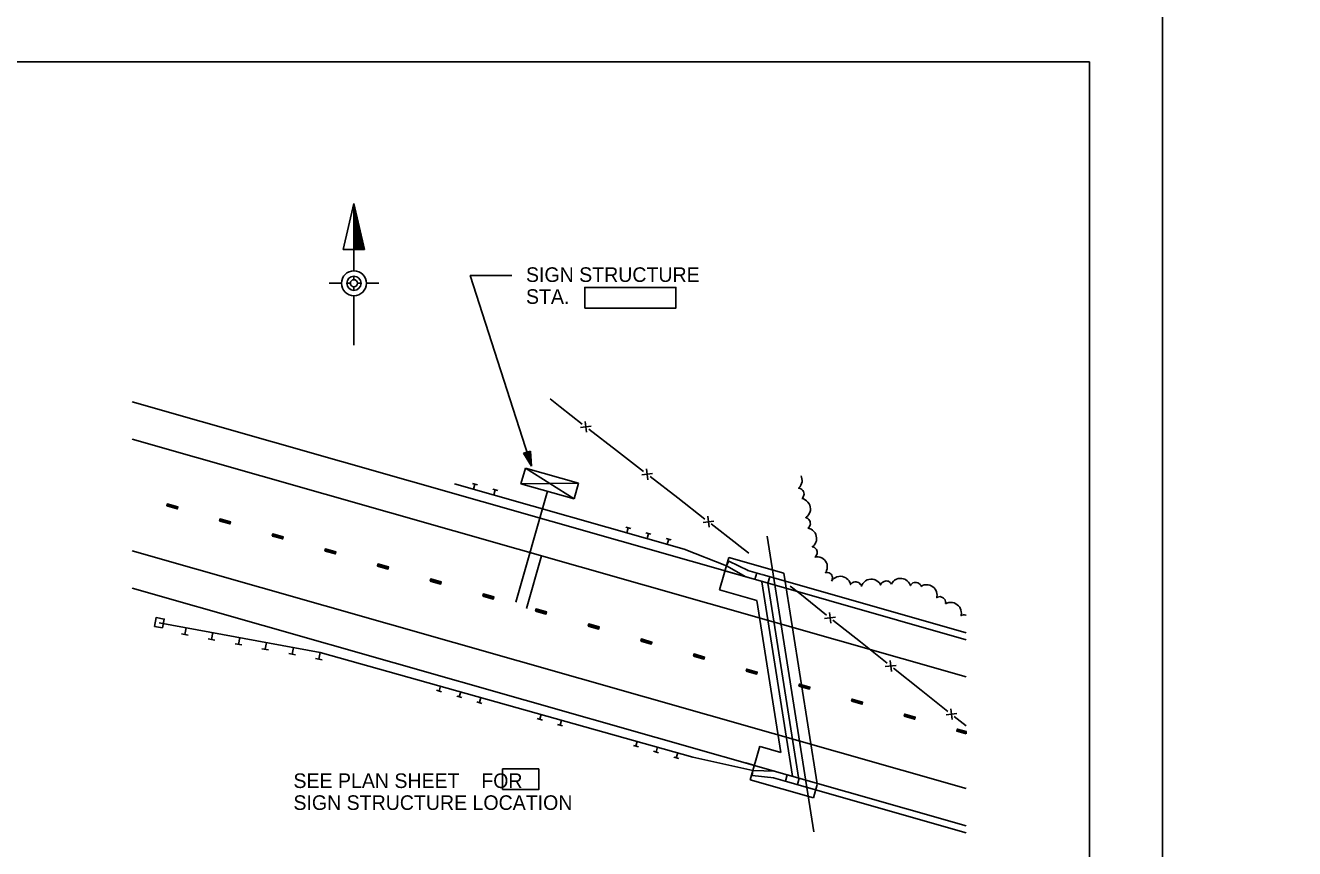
# Model space of a CAD drawing. Extents: x 640117 to 642655, y 297247 to 298435.
# Drawn here: x 640724.9 to 640985.6, y 297665 to 297834 of the extents above; entities that cross this region are included whole.
import ezdxf

# ---------------------------------------------------------------- set-up
doc = ezdxf.new("R2010")
doc.units = 0
for name, color, linetype in [('10', 7, 'Continuous'), ('2', 7, 'Continuous'), ('20', 7, 'Continuous'), ('21', 7, 'Continuous'), ('26', 7, 'Continuous'), ('27', 7, 'Continuous'), ('43', 7, 'Continuous'), ('48', 7, 'Continuous'), ('50', 7, 'Continuous'), ('51', 7, 'Continuous'), ('52', 7, 'Continuous'), ('53', 7, 'Continuous'), ('PLT-BNDY', 7, 'Continuous')]:
    doc.layers.add(name, color=color, linetype=linetype)

msp = doc.modelspace()

# ---------------------------------------------------------------- linework, layer by layer
at = {"layer": '10'}
msp.add_lwpolyline([(640828.84, 297743.48), (640816.31, 297782.59), (640824.86, 297782.59)], dxfattribs=at)
at = {"layer": '2'}
for p, q in [((640157.46, 297826.46), (640943.46, 297826.46)), ((640943.46, 297826.46), (640943.46, 297262.46))]:
    msp.add_line(p, q, dxfattribs=at)
for points in [[(640839.82, 297775.92), (640858.53, 297775.92), (640858.53, 297780.17), (640839.82, 297780.17)], [(640822.93, 297677.07), (640830.35, 297677.07), (640830.35, 297681.32), (640822.93, 297681.32)]]:
    msp.add_lwpolyline(points, close=True, dxfattribs=at)
at = {"layer": '20'}
for points in [[(640884.22, 297741.47), (640884.32, 297741.23), (640884.4, 297740.87), (640884.44, 297740.52), (640884.42, 297740.27), (640884.34, 297739.93), (640884.2, 297739.58), (640884.02, 297739.3), (640883.84, 297739.08), (640883.7, 297738.94), (640883.89, 297738.93), (640884.15, 297738.82), (640884.4, 297738.66), (640884.58, 297738.45), (640884.7, 297738.24), (640884.78, 297738.01), (640884.84, 297737.75), (640884.82, 297737.55), (640884.69, 297737.18), (640884.6, 297736.99), (640884.42, 297736.82)], [(640884.41, 297736.82), (640884.72, 297736.74), (640885.08, 297736.58), (640885.35, 297736.38), (640885.65, 297736.09), (640885.87, 297735.77), (640886.02, 297735.46), (640886.1, 297735.09), (640886.14, 297734.73), (640886.13, 297734.38), (640886.07, 297734.14), (640885.95, 297733.81), (640885.76, 297733.49), (640885.55, 297733.23), (640885.34, 297733.04), (640885.18, 297732.93), (640885.37, 297732.88), (640885.62, 297732.74), (640885.83, 297732.55), (640885.99, 297732.32), (640886.08, 297732.1), (640886.12, 297731.85), (640886.14, 297731.59), (640886.11, 297731.4), (640885.93, 297731.05), (640885.8, 297730.87), (640885.61, 297730.73)], [(640885.61, 297730.73), (640885.92, 297730.67), (640886.28, 297730.53), (640886.56, 297730.35), (640886.86, 297730.07), (640887.11, 297729.77), (640887.26, 297729.47), (640887.36, 297729.11), (640887.41, 297728.76), (640887.42, 297728.41), (640887.37, 297728.17), (640887.26, 297727.84), (640887.09, 297727.52), (640886.89, 297727.25), (640886.68, 297727.05), (640886.53, 297726.93), (640886.72, 297726.89), (640886.97, 297726.77), (640887.2, 297726.59), (640887.37, 297726.37), (640887.47, 297726.16), (640887.52, 297725.93), (640887.56, 297725.66), (640887.52, 297725.47), (640887.36, 297725.12), (640887.24, 297724.94), (640887.06, 297724.79)], [(640887.06, 297724.79), (640887.36, 297724.85), (640887.75, 297724.85), (640888.08, 297724.78), (640888.46, 297724.64), (640888.79, 297724.45), (640889.04, 297724.23), (640889.26, 297723.94), (640889.43, 297723.64), (640889.56, 297723.32), (640889.6, 297723.07), (640889.61, 297722.74), (640889.56, 297722.37), (640889.46, 297722.06), (640889.35, 297721.8), (640889.24, 297721.64), (640889.43, 297721.67), (640889.71, 297721.65), (640889.99, 297721.57), (640890.22, 297721.42), (640890.38, 297721.27), (640890.52, 297721.08), (640890.63, 297720.84), (640890.68, 297720.66), (640890.64, 297720.27), (640890.6, 297720.07), (640890.47, 297719.86)], [(640890.47, 297719.86), (640890.65, 297720.12), (640890.93, 297720.39), (640891.22, 297720.58), (640891.6, 297720.74), (640891.99, 297720.84), (640892.33, 297720.86), (640892.71, 297720.81), (640893.06, 297720.71), (640893.39, 297720.58), (640893.59, 297720.43), (640893.85, 297720.21), (640894.09, 297719.91), (640894.25, 297719.62), (640894.36, 297719.36), (640894.4, 297719.16), (640894.52, 297719.32), (640894.73, 297719.5), (640894.99, 297719.65), (640895.27, 297719.71), (640895.51, 297719.71), (640895.75, 297719.66), (640896, 297719.59), (640896.16, 297719.49), (640896.43, 297719.19), (640896.55, 297719.01), (640896.62, 297718.78)], [(640896.62, 297718.78), (640896.73, 297719.07), (640896.93, 297719.4), (640897.16, 297719.65), (640897.48, 297719.91), (640897.82, 297720.11), (640898.15, 297720.21), (640898.52, 297720.25), (640898.88, 297720.25), (640899.23, 297720.2), (640899.47, 297720.11), (640899.77, 297719.95), (640900.07, 297719.72), (640900.3, 297719.49), (640900.46, 297719.25), (640900.56, 297719.08), (640900.63, 297719.26), (640900.79, 297719.49), (640901.01, 297719.69), (640901.26, 297719.82), (640901.49, 297719.88), (640901.73, 297719.9), (640901.99, 297719.89), (640902.17, 297719.83), (640902.51, 297719.61), (640902.67, 297719.47), (640902.78, 297719.25)], [(640902.78, 297719.25), (640902.94, 297719.53), (640903.18, 297719.83), (640903.44, 297720.04), (640903.8, 297720.24), (640904.16, 297720.38), (640904.49, 297720.43), (640904.86, 297720.42), (640905.21, 297720.36), (640905.55, 297720.27), (640905.77, 297720.14), (640906.04, 297719.94), (640906.3, 297719.67), (640906.49, 297719.4), (640906.61, 297719.14), (640906.68, 297718.96), (640906.78, 297719.13), (640906.96, 297719.34), (640907.21, 297719.5), (640907.47, 297719.59), (640907.7, 297719.62), (640907.94, 297719.59), (640908.2, 297719.55), (640908.37, 297719.46), (640908.66, 297719.19), (640908.79, 297719.03), (640908.87, 297718.8)], [(640908.87, 297718.8), (640909.15, 297718.95), (640909.52, 297719.08), (640909.85, 297719.12), (640910.26, 297719.11), (640910.65, 297719.03), (640910.97, 297718.91), (640911.28, 297718.7), (640911.55, 297718.46), (640911.78, 297718.2), (640911.91, 297717.98), (640912.03, 297717.67), (640912.12, 297717.3), (640912.14, 297716.97), (640912.12, 297716.69), (640912.08, 297716.49), (640912.25, 297716.59), (640912.52, 297716.66), (640912.81, 297716.68), (640913.09, 297716.61), (640913.3, 297716.52), (640913.5, 297716.38), (640913.69, 297716.19), (640913.8, 297716.02), (640913.9, 297715.64), (640913.93, 297715.44), (640913.89, 297715.2)], [(640913.89, 297715.2), (640914.16, 297715.34), (640914.54, 297715.46), (640914.88, 297715.49), (640915.29, 297715.47), (640915.68, 297715.38), (640915.99, 297715.24), (640916.3, 297715.03), (640916.57, 297714.78), (640916.81, 297714.52), (640916.92, 297714.29), (640917.05, 297713.96), (640917.12, 297713.6), (640917.14, 297713.27), (640917.11, 297712.98), (640917.07, 297712.79), (640917.24, 297712.88), (640917.52, 297712.94), (640917.81, 297712.95), (640918.09, 297712.88), (640918.14, 297712.85)]]:
    msp.add_lwpolyline(points, dxfattribs=at)
at = {"layer": '21'}
for p, q in [((640839.89, 297752.66), (640840.18, 297750.42)), ((640838.92, 297751.4), (640841.15, 297751.68)), ((640852.47, 297742.92), (640852.76, 297740.68)), ((640851.51, 297741.66), (640853.73, 297741.95)), ((640864.09, 297731.91), (640866.32, 297732.2)), ((640865.06, 297733.18), (640865.34, 297730.94)), ((640890.06, 297713.46), (640890.31, 297711.22)), ((640889.07, 297712.21), (640891.3, 297712.47)), ((640902.52, 297703.57), (640902.77, 297701.33)), ((640901.53, 297702.32), (640903.76, 297702.58)), ((640913.99, 297692.42), (640916.23, 297692.68)), ((640914.98, 297693.67), (640915.24, 297691.43))]:
    msp.add_line(p, q, dxfattribs=at)
for points in [[(640832.69, 297757.26), (640833.74, 297756.44)], [(640833.73, 297756.44), (640834.73, 297755.64), (640839.31, 297752.1)], [(640840.62, 297751.09), (640846.31, 297746.68)], [(640846.31, 297746.68), (640851.89, 297742.36)], [(640853.21, 297741.35), (640858.9, 297736.94)], [(640858.9, 297736.94), (640864.48, 297732.62)], [(640865.78, 297731.61), (640871.06, 297727.53), (640871.47, 297727.19)], [(640871.47, 297727.19), (640873.47, 297725.61)], [(640882, 297718.84), (640883.94, 297717.3)], [(640883.94, 297717.3), (640889.46, 297712.91)], [(640890.76, 297711.88), (640896.4, 297707.4)], [(640896.4, 297707.4), (640901.92, 297703.02)], [(640903.22, 297701.99), (640908.86, 297697.51)], [(640908.86, 297697.51), (640914.39, 297693.12)], [(640915.68, 297692.09), (640918.14, 297690.14)]]:
    msp.add_lwpolyline(points, dxfattribs=at)
at = {"layer": '26'}
for p, q in [((640746.87, 297756.65), (640875.82, 297719.91)), ((640746.87, 297749.01), (640918.14, 297700.21)), ((640746.87, 297726.09), (640918.14, 297677.29)), ((640746.87, 297718.45), (640881.39, 297680.12))]:
    msp.add_line(p, q, dxfattribs=at)
at = {"layer": '27'}
for p, q in [((640860.2, 297726.45), (640813.07, 297739.87)), ((640817.79, 297739.64), (640816.75, 297739.93)), ((640817.27, 297739.79), (640816.98, 297738.75)), ((640821.94, 297738.47), (640820.9, 297738.76)), ((640821.42, 297738.61), (640821.13, 297737.58)), ((640849.26, 297730.67), (640848.22, 297730.97)), ((640848.74, 297730.82), (640848.45, 297729.78)), ((640853.41, 297729.5), (640852.37, 297729.8)), ((640852.89, 297729.65), (640852.6, 297728.61)), ((640857.56, 297728.33), (640856.52, 297728.62)), ((640857.04, 297728.48), (640856.75, 297727.44)), ((640868.92, 297723.01), (640860.2, 297726.45)), ((640785.47, 297705.21), (640752.44, 297711.33)), ((640758.38, 297708.8), (640757, 297709.06)), ((640757.69, 297708.93), (640757.94, 297710.3)), ((640763.19, 297707.91), (640763.45, 297709.29)), ((640768.7, 297706.89), (640768.95, 297708.27)), ((640763.88, 297707.78), (640762.51, 297708.04)), ((640769.39, 297706.76), (640768.01, 297707.02)), ((640774.89, 297705.74), (640773.52, 297706)), ((640774.2, 297705.87), (640774.46, 297707.25)), ((640779.71, 297704.85), (640779.97, 297706.23)), ((640780.4, 297704.73), (640779.02, 297704.98)), ((640785.89, 297703.71), (640784.52, 297703.96)), ((640785.2, 297703.84), (640785.46, 297705.21)), ((640809.88, 297697.31), (640810.18, 297698.35)), ((640810.4, 297697.17), (640809.36, 297697.46)), ((640814.55, 297695.97), (640813.51, 297696.27)), ((640814.03, 297696.12), (640814.33, 297697.16)), ((640818.17, 297694.93), (640818.47, 297695.97)), ((640818.69, 297694.78), (640817.66, 297695.08)), ((640830.59, 297691.5), (640830.88, 297692.54)), ((640831.1, 297691.36), (640830.07, 297691.65)), ((640835.25, 297690.16), (640834.21, 297690.46)), ((640834.73, 297690.31), (640835.03, 297691.35)), ((640850.82, 297685.82), (640849.79, 297686.12)), ((640850.3, 297685.97), (640850.6, 297687.01)), ((640854.97, 297684.63), (640853.93, 297684.93)), ((640854.45, 297684.78), (640854.75, 297685.82)), ((640859.11, 297683.44), (640858.08, 297683.74)), ((640858.6, 297683.59), (640858.89, 297684.63))]:
    msp.add_line(p, q, dxfattribs=at)
msp.add_lwpolyline([(640753.13, 297710.26), (640753.47, 297712.07), (640751.8, 297712.37), (640751.46, 297710.57)], close=True, dxfattribs=at)
msp.add_lwpolyline([(640785.47, 297705.21), (640862.03, 297683.73), (640874.35, 297681)], dxfattribs=at)
at = {"layer": '43'}
for p, q in [((640826.7, 297739.86), (640827.62, 297743.09)), ((640827.62, 297743.09), (640838.53, 297739.98)), ((640827.62, 297743.09), (640837.61, 297736.76)), ((640838.53, 297739.98), (640826.7, 297739.86)), ((640826.7, 297739.86), (640837.61, 297736.76)), ((640837.61, 297736.75), (640838.52, 297739.98)), ((640825.68, 297715.58), (640832.15, 297738.31)), ((640827.86, 297714.26), (640830.93, 297725.05))]:
    msp.add_line(p, q, dxfattribs=at)
at = {"layer": '48'}
for points in [[(640753.97, 297735.3), (640756.13, 297734.68), (640756.25, 297735.12), (640754.09, 297735.73)], [(640754.03, 297735.33), (640756.1, 297734.74), (640756.19, 297735.08), (640754.12, 297735.66)], [(640754.09, 297735.36), (640756.06, 297734.8), (640756.13, 297735.04), (640754.15, 297735.61)], [(640754.14, 297735.4), (640756.04, 297734.86), (640756.08, 297735.02), (640754.19, 297735.55)], [(640754.18, 297735.42), (640756.01, 297734.9), (640756.04, 297734.99), (640754.21, 297735.51)], [(640754.22, 297735.44), (640755.98, 297734.93), (640756, 297734.97), (640754.23, 297735.47)], [(640764.78, 297732.21), (640766.94, 297731.6), (640767.07, 297732.03), (640764.91, 297732.65)], [(640764.84, 297732.25), (640766.91, 297731.66), (640767.01, 297732), (640764.94, 297732.59)], [(640764.91, 297732.28), (640766.88, 297731.72), (640766.95, 297731.96), (640764.97, 297732.52)], [(640764.95, 297732.31), (640766.85, 297731.78), (640766.89, 297731.93), (640765, 297732.47)], [(640764.99, 297732.34), (640766.83, 297731.81), (640766.86, 297731.91), (640765.03, 297732.43)], [(640765.04, 297732.35), (640766.8, 297731.85), (640766.81, 297731.89), (640765.05, 297732.39)], [(640775.6, 297729.13), (640777.76, 297728.52), (640777.88, 297728.95), (640775.73, 297729.57)], [(640775.66, 297729.16), (640777.73, 297728.57), (640777.82, 297728.92), (640775.76, 297729.51)], [(640775.72, 297729.2), (640777.7, 297728.64), (640777.76, 297728.88), (640775.79, 297729.44)], [(640775.77, 297729.23), (640777.66, 297728.69), (640777.72, 297728.85), (640775.82, 297729.39)], [(640775.82, 297729.25), (640777.64, 297728.73), (640777.67, 297728.83), (640775.84, 297729.35)], [(640775.85, 297729.27), (640777.62, 297728.77), (640777.63, 297728.81), (640775.86, 297729.31)], [(640786.42, 297726.05), (640788.58, 297725.44), (640788.7, 297725.87), (640786.54, 297726.48)], [(640786.47, 297726.08), (640788.54, 297725.49), (640788.64, 297725.84), (640786.57, 297726.43)], [(640786.53, 297726.12), (640788.51, 297725.56), (640788.58, 297725.8), (640786.61, 297726.36)], [(640786.59, 297726.15), (640788.48, 297725.61), (640788.52, 297725.77), (640786.63, 297726.31)], [(640786.63, 297726.17), (640788.46, 297725.65), (640788.49, 297725.74), (640786.65, 297726.27)], [(640786.67, 297726.19), (640788.44, 297725.69), (640788.45, 297725.72), (640786.68, 297726.22)], [(640797.23, 297722.97), (640799.4, 297722.35), (640799.52, 297722.78), (640797.35, 297723.4)], [(640797.29, 297723.01), (640799.36, 297722.41), (640799.46, 297722.75), (640797.38, 297723.34)], [(640797.35, 297723.04), (640799.33, 297722.48), (640799.4, 297722.72), (640797.42, 297723.28)], [(640797.4, 297723.06), (640799.3, 297722.52), (640799.34, 297722.69), (640797.45, 297723.23)], [(640797.45, 297723.09), (640799.27, 297722.56), (640799.3, 297722.66), (640797.48, 297723.19)], [(640797.48, 297723.11), (640799.25, 297722.6), (640799.26, 297722.64), (640797.49, 297723.15)], [(640808.05, 297719.88), (640810.21, 297719.27), (640810.33, 297719.7), (640808.17, 297720.32)], [(640808.1, 297719.92), (640810.17, 297719.33), (640810.27, 297719.67), (640808.2, 297720.26)], [(640808.17, 297719.95), (640810.14, 297719.39), (640810.21, 297719.63), (640808.23, 297720.2)], [(640808.22, 297719.98), (640810.12, 297719.44), (640810.16, 297719.61), (640808.27, 297720.14)], [(640808.26, 297720), (640810.1, 297719.49), (640810.12, 297719.58), (640808.29, 297720.1)], [(640808.3, 297720.03), (640810.07, 297719.52), (640810.08, 297719.56), (640808.31, 297720.07)], [(640818.87, 297716.8), (640821.02, 297716.19), (640821.15, 297716.62), (640818.99, 297717.24)], [(640818.92, 297716.84), (640820.99, 297716.25), (640821.09, 297716.59), (640819.02, 297717.18)], [(640818.99, 297716.87), (640820.96, 297716.31), (640821.03, 297716.55), (640819.05, 297717.12)], [(640819.03, 297716.9), (640820.93, 297716.36), (640820.98, 297716.52), (640819.08, 297717.06)], [(640819.08, 297716.92), (640820.9, 297716.41), (640820.93, 297716.5), (640819.11, 297717.02)], [(640819.12, 297716.95), (640820.88, 297716.44), (640820.89, 297716.48), (640819.13, 297716.98)], [(640829.68, 297713.72), (640831.84, 297713.1), (640831.97, 297713.54), (640829.8, 297714.15)], [(640829.74, 297713.76), (640831.81, 297713.17), (640831.9, 297713.5), (640829.83, 297714.09)], [(640829.8, 297713.79), (640831.77, 297713.23), (640831.84, 297713.47), (640829.87, 297714.03)], [(640829.85, 297713.81), (640831.74, 297713.28), (640831.79, 297713.44), (640829.9, 297713.99)], [(640829.89, 297713.84), (640831.72, 297713.32), (640831.75, 297713.42), (640829.92, 297713.94)], [(640829.93, 297713.86), (640831.7, 297713.36), (640831.71, 297713.39), (640829.94, 297713.9)], [(640840.49, 297710.64), (640842.66, 297710.02), (640842.78, 297710.46), (640840.62, 297711.07)], [(640840.55, 297710.67), (640842.62, 297710.08), (640842.72, 297710.42), (640840.65, 297711.01)], [(640840.61, 297710.7), (640842.59, 297710.14), (640842.66, 297710.39), (640840.69, 297710.95)], [(640840.67, 297710.73), (640842.56, 297710.2), (640842.61, 297710.36), (640840.71, 297710.9)], [(640840.71, 297710.76), (640842.54, 297710.24), (640842.57, 297710.34), (640840.74, 297710.85)], [(640840.75, 297710.78), (640842.52, 297710.28), (640842.53, 297710.32), (640840.76, 297710.82)], [(640851.31, 297707.56), (640853.47, 297706.94), (640853.6, 297707.37), (640851.43, 297707.99)], [(640851.37, 297707.59), (640853.44, 297707), (640853.54, 297707.34), (640851.46, 297707.93)], [(640851.43, 297707.62), (640853.4, 297707.06), (640853.48, 297707.31), (640851.5, 297707.87)], [(640851.48, 297707.66), (640853.38, 297707.11), (640853.42, 297707.28), (640851.53, 297707.82)], [(640851.53, 297707.68), (640853.36, 297707.16), (640853.38, 297707.25), (640851.56, 297707.78)], [(640851.56, 297707.7), (640853.33, 297707.2), (640853.34, 297707.23), (640851.57, 297707.73)], [(640862.13, 297704.48), (640864.29, 297703.86), (640864.41, 297704.29), (640862.25, 297704.91)], [(640862.18, 297704.51), (640864.26, 297703.92), (640864.35, 297704.26), (640862.28, 297704.85)], [(640862.25, 297704.55), (640864.22, 297703.98), (640864.29, 297704.22), (640862.32, 297704.79)], [(640862.3, 297704.57), (640864.2, 297704.03), (640864.24, 297704.2), (640862.35, 297704.74)], [(640862.35, 297704.59), (640864.17, 297704.07), (640864.2, 297704.17), (640862.37, 297704.7)], [(640862.38, 297704.62), (640864.15, 297704.11), (640864.16, 297704.15), (640862.39, 297704.65)], [(640872.94, 297701.39), (640875.1, 297700.78), (640875.23, 297701.21), (640873.07, 297701.83)], [(640873, 297701.42), (640875.07, 297700.84), (640875.17, 297701.18), (640873.1, 297701.77)], [(640873.07, 297701.46), (640875.04, 297700.9), (640875.11, 297701.14), (640873.13, 297701.7)], [(640873.11, 297701.49), (640875.01, 297700.95), (640875.05, 297701.11), (640873.16, 297701.65)], [(640873.15, 297701.51), (640874.99, 297700.99), (640875.01, 297701.09), (640873.18, 297701.61)], [(640873.19, 297701.53), (640874.96, 297701.03), (640874.98, 297701.07), (640873.21, 297701.57)], [(640883.76, 297698.31), (640885.93, 297697.7), (640886.05, 297698.13), (640883.88, 297698.74)], [(640883.82, 297698.35), (640885.89, 297697.75), (640885.98, 297698.1), (640883.92, 297698.69)], [(640883.88, 297698.38), (640885.85, 297697.82), (640885.93, 297698.06), (640883.95, 297698.63)], [(640883.94, 297698.41), (640885.82, 297697.87), (640885.87, 297698.03), (640883.98, 297698.57)], [(640883.98, 297698.43), (640885.8, 297697.91), (640885.83, 297698.01), (640884, 297698.53)], [(640884.01, 297698.45), (640885.78, 297697.95), (640885.79, 297697.99), (640884.02, 297698.49)], [(640894.57, 297695.23), (640896.74, 297694.61), (640896.86, 297695.05), (640894.7, 297695.67)], [(640894.64, 297695.27), (640896.7, 297694.67), (640896.8, 297695.01), (640894.73, 297695.6)], [(640894.7, 297695.3), (640896.67, 297694.73), (640896.74, 297694.98), (640894.77, 297695.54)], [(640894.74, 297695.32), (640896.64, 297694.79), (640896.69, 297694.95), (640894.79, 297695.49)], [(640894.79, 297695.35), (640896.62, 297694.83), (640896.65, 297694.92), (640894.82, 297695.45)], [(640894.83, 297695.37), (640896.6, 297694.87), (640896.61, 297694.9), (640894.84, 297695.41)], [(640905.39, 297692.15), (640907.55, 297691.53), (640907.68, 297691.96), (640905.51, 297692.59)], [(640905.45, 297692.18), (640907.52, 297691.59), (640907.62, 297691.93), (640905.55, 297692.52)], [(640905.51, 297692.21), (640907.49, 297691.65), (640907.55, 297691.9), (640905.58, 297692.46)], [(640905.56, 297692.24), (640907.46, 297691.7), (640907.5, 297691.87), (640905.62, 297692.4)], [(640905.61, 297692.27), (640907.43, 297691.75), (640907.46, 297691.84), (640905.64, 297692.37)], [(640905.65, 297692.28), (640907.41, 297691.79), (640907.42, 297691.82), (640905.65, 297692.33)]]:
    msp.add_lwpolyline(points, close=True, dxfattribs=at)
for points in [[(640918.14, 297688.98), (640916.33, 297689.5), (640916.21, 297689.07), (640918.14, 297688.51)], [(640918.14, 297688.93), (640916.36, 297689.44), (640916.26, 297689.1), (640918.14, 297688.57)], [(640918.14, 297688.88), (640916.39, 297689.38), (640916.33, 297689.13), (640918.14, 297688.62)], [(640918.14, 297688.84), (640916.42, 297689.32), (640916.38, 297689.16), (640918.14, 297688.66)], [(640918.14, 297688.8), (640916.45, 297689.28), (640916.42, 297689.19), (640918.14, 297688.7)], [(640918.14, 297688.77), (640916.47, 297689.24), (640916.46, 297689.21), (640918.14, 297688.73)], [(640918.14, 297688.51), (640918.14, 297688.98)], [(640918.14, 297688.57), (640918.14, 297688.93)], [(640918.14, 297688.62), (640918.14, 297688.88)], [(640918.14, 297688.66), (640918.14, 297688.84)], [(640918.14, 297688.7), (640918.14, 297688.8)], [(640918.14, 297688.73), (640918.14, 297688.77)]]:
    msp.add_lwpolyline(points, dxfattribs=at)
at = {"layer": '50'}
msp.add_line((640877.27, 297729.08), (640886.86, 297668.38), dxfattribs=at)
at = {"layer": '51'}
for p, q in [((640867.51, 297718.05), (640869.4, 297724.7)), ((640868.92, 297723.01), (640869.39, 297723.96)), ((640869.39, 297723.96), (640873.36, 297722.04)), ((640869.4, 297724.7), (640880.72, 297721.47)), ((640868.75, 297721.92), (640875.82, 297719.91)), ((640872.86, 297720.75), (640868.92, 297723.01)), ((640873.31, 297722.05), (640876.2, 297721.23)), ((640875.11, 297721.54), (640874.73, 297720.22)), ((640876.24, 297721.22), (640918.14, 297709.28)), ((640880.72, 297721.47), (640887.55, 297678.25)), ((640875.86, 297719.9), (640918.14, 297707.85)), ((640876.18, 297719.72), (640882.49, 297679.81)), ((640877.79, 297720.78), (640877.42, 297719.46)), ((640877.42, 297719.46), (640883.79, 297679.12)), ((640867.51, 297718.05), (640875.17, 297715.86)), ((640875.17, 297715.86), (640880.09, 297684.72)), ((640875.74, 297685.96), (640873.76, 297679.06)), ((640875.86, 297685.92), (640880.09, 297684.72)), ((640874.75, 297682.01), (640872.89, 297682.54)), ((640874.32, 297681.01), (640874.21, 297679.94)), ((640874.21, 297679.94), (640878.6, 297679.49)), ((640878.83, 297680.85), (640874.35, 297681)), ((640878.55, 297679.5), (640881.44, 297678.67)), ((640881.01, 297678.79), (640881.39, 297680.12)), ((640881.39, 297680.12), (640918.14, 297669.64)), ((640873.76, 297679.06), (640886.76, 297675.36)), ((640881.47, 297678.66), (640918.14, 297668.21)), ((640883.5, 297678.09), (640883.79, 297679.12)), ((640886.76, 297675.36), (640887.54, 297678.12))]:
    msp.add_line(p, q, dxfattribs=at)
at = {"layer": '52'}
for p, q in [((640828.68, 297746.57), (640827.24, 297746.13)), ((640827.24, 297746.13), (640828.84, 297743.48)), ((640828.51, 297746.33), (640827.51, 297746.02)), ((640827.51, 297746.02), (640828.62, 297744.18)), ((640828.35, 297746.09), (640827.78, 297745.92)), ((640827.78, 297745.92), (640828.41, 297744.88)), ((640828, 297745.91), (640828.19, 297745.58)), ((640828.19, 297745.58), (640828.18, 297745.95)), ((640828.41, 297744.88), (640828.35, 297746.09)), ((640828.62, 297744.18), (640828.51, 297746.33)), ((640828.84, 297743.48), (640828.68, 297746.57))]:
    msp.add_line(p, q, dxfattribs=at)
at = {"layer": '53'}
for p, q in [((640790.22, 297787.93), (640792.41, 297797.39)), ((640794.59, 297787.93), (640792.41, 297797.39)), ((640792.41, 297783.57), (640792.41, 297797.39)), ((640794.59, 297787.93), (640790.22, 297787.93)), ((640792.41, 297781.75), (640792.41, 297782.47)), ((640789.86, 297781.02), (640787.31, 297781.02)), ((640791.7, 297781.02), (640790.96, 297781.02)), ((640792.41, 297781.02), (640792.41, 297781.02)), ((640792.41, 297779.58), (640792.41, 297780.29)), ((640793.87, 297781.02), (640793.12, 297781.02)), ((640797.5, 297781.02), (640794.94, 297781.02)), ((640792.41, 297768.28), (640792.41, 297778.46))]:
    msp.add_line(p, q, dxfattribs=at)
msp.add_lwpolyline([(640792.51, 297796.72), (640792.51, 297787.99), (640794.48, 297787.99), (640792.62, 297796.29), (640792.62, 297788.1), (640794.37, 297788.1), (640792.73, 297795.41), (640792.73, 297788.21), (640794.26, 297788.21), (640792.84, 297794.65), (640792.84, 297788.32), (640794.15, 297788.32), (640792.95, 297793.77), (640792.95, 297788.42), (640794.04, 297788.42), (640793.06, 297793.01), (640793.06, 297788.54), (640793.93, 297788.54), (640793.17, 297792.14), (640793.17, 297788.64), (640793.83, 297788.64), (640793.28, 297791.37), (640793.28, 297788.75), (640793.72, 297788.75), (640793.39, 297790.5), (640793.39, 297788.86), (640793.61, 297788.86), (640793.5, 297789.52), (640793.5, 297788.97), (640792.51, 297787.99), (640792.51, 297796.72), (640793.5, 297789.52), (640793.5, 297788.97), (640794.48, 297787.99)], dxfattribs=at)
for radius in [2.55, 1.46, 0.728]:
    msp.add_circle((640792.41, 297781.02), radius, dxfattribs=at)
at = {"layer": 'PLT-BNDY'}
for points in [[(640117.46, 297841.46), (640958.46, 297841.46), (640958.46, 297247.46), (640117.46, 297247.46)], [(640958.46, 297841.46), (641799.46, 297841.46), (641799.46, 297247.46), (640958.46, 297247.46)]]:
    msp.add_lwpolyline(points, close=True, dxfattribs=at)

# ---------------------------------------------------------------- texts
at = {"layer": '2'}
for s, p in [('SIGN STRUCTURE', (640827.74, 297781.29)), ('STA.', (640827.74, 297776.79)), ('SEE PLAN SHEET    FOR', (640779.99, 297677.4)), ('SIGN STRUCTURE LOCATION', (640779.99, 297672.9))]:
    msp.add_text(s, height=3, dxfattribs=at).set_placement(p)

doc.saveas('drawing.dxf')
